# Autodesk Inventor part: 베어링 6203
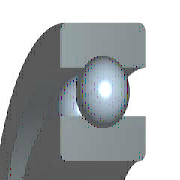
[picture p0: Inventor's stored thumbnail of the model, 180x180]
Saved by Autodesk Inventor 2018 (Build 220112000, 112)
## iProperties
IsCustomPart: 0
Created: 2016-04
Part Number: 베어링 6203
Material: 강철, 연강
Description: 깊은 그루브 볼 베어링
Document SubType Name: Modeling
Standard: KS B 2023
Designer: mdu
Standards Organization: KS
Language: ko-KR
Size Designation: 6203 - 17 x 40 x 12
Categories: <MemberInstance><Categories><Category DisplayName="샤프트 부품" InternalName="7f7aeb1f-a693-4053-b835-cee3144e0d98" Mnemonic="SHFT"><Category DisplayName="베어링" Inter
Density: 7.86 g/cm^3
Mass: 64.9809 g
Surface Area: 64.3582 cm^2
Volume: 8.26729 cm^3
Appearance: 노란색
Author: mdu
Revision Number: 1
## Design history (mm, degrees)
sketch "스케치" dims "d0" = 5.98 (= -0.26 x WD + 0.26 x BD)
  geometry: L1 (3.01, 14.25)-(8.99, 14.25); L2 (6, 14.25)-(6, 11.26); L3 (6, 14.25)-(6, 17.24); L4 (3.778, 12.249)-(0, 12.249); L5 (0, 8.5)-(12, 8.5); L6 (3.778, 16.251)-(0, 16.251); L7 (0, 20)-(12, 20); L8 (12, 8.5)-(12, 12.249); L9 (8.222, 12.249)-(12, 12.249); L10 (8.222, 16.251)-(12, 16.251); L11 (12, 20)-(12, 16.251); L12 (-1.4, 0)-(8.4, 0) reference; L13 (0, -0.3)-(0, 5.3) reference
  constraints: 22 end point, 4 point on line, 2 collinear, 2 perpendicular, 2 symmetric about line, 1 midpoint, 1 parallel, 14 other
  dimensions: "d9" = 17 diameter of L5 L12 (= WD); "d11" = 40 diameter of L7 L12 (= BD); "d12" = 12 distance between parallel lines of L8 L13 (= KB); "d13" = 24.498 diameter of L9 L12 (= 0.326 x BD + 0.674 x WD)
revolve "본체" stored, may be unused: angle "d6" = 90 deg
revolve "볼" stored, may be unused: angle "d7" = 90 deg
pattern_circular "IDS_ARRAYBALL[SIMPL:T]" dims angle "d3" = 360 deg
body "Solid1"
fillet "모깎기1" dims "d1" = 0.6 (= KRS)
other parameters: "WD" = 17 [user parameter; used in 5 equation terms], "BD" = 40 [user parameter; used in 5 equation terms], "KB" = 12 [user parameter; used in 1 equation term], "KRS" = 0.6 [user parameter; used in 1 equation term], "d4" = 0, "d5" = 0, "d8" = 0, "d14" = 0, "d15" = 0, "BBA" = 0 [user parameter], "BC0" = 4750000 [user parameter], "BC" = 9560000 [user parameter], "WR" = 8.5 (= 0.5 x WD) [user parameter]
